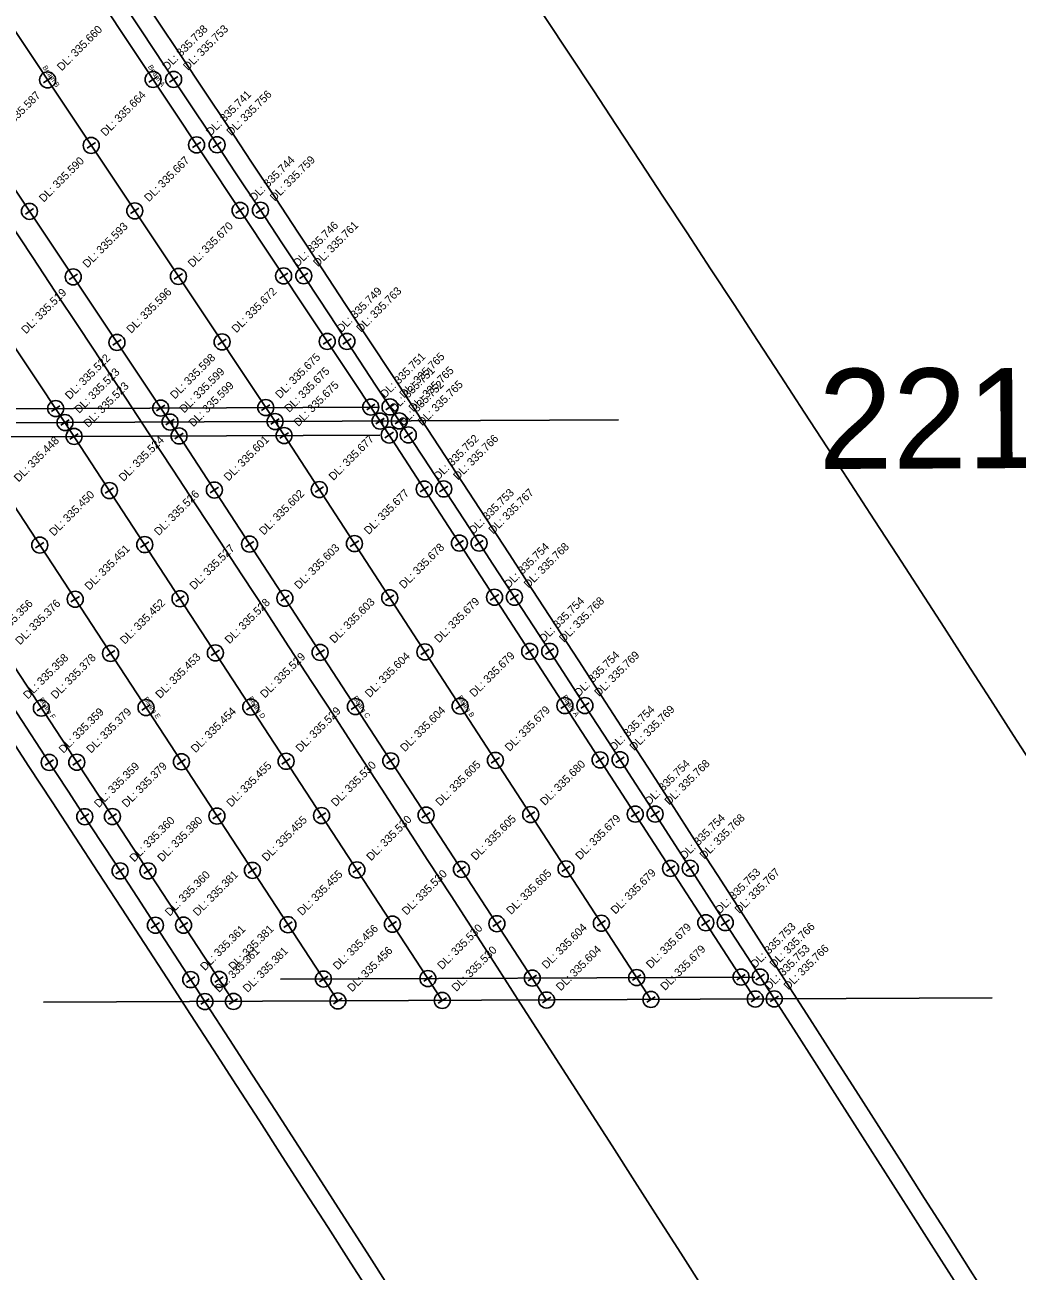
# Model space of a CAD drawing. Extents: x 1524497 to 1524592, y 1103688 to 1103812.
# Drawn here: x 1524545.51 to 1524570.33, y 1103718.69 to 1103749.84 of the extents above; entities that cross this region are included whole.
import ezdxf

# ---------------------------------------------------------------- set-up
doc = ezdxf.new("R2010")
doc.units = 0
doc.layers.add('Level 1', color=7, linetype='Continuous')

msp = doc.modelspace()

# ---------------------------------------------------------------- linework, layer by layer
at = {"layer": 'Level 1'}
for p, q in [((1524535.113, 1103756.948), (1524546.512, 1103739.9)), ((1524537.761, 1103756.96), (1524549.14, 1103739.912)), ((1524540.409, 1103756.972), (1524551.767, 1103739.924)), ((1524543.057, 1103756.984), (1524554.394, 1103739.936)), ((1524545.974, 1103748.394), (1524546.182, 1103748.533)), ((1524548.611, 1103748.406), (1524548.819, 1103748.545)), ((1524549.334, 1103748.547), (1524549.126, 1103748.409)), ((1524547.063, 1103746.759), (1524547.271, 1103746.897)), ((1524549.699, 1103746.771), (1524549.907, 1103746.909)), ((1524550.42, 1103746.912), (1524550.212, 1103746.773)), ((1524545.52, 1103745.109), (1524545.728, 1103745.248)), ((1524548.154, 1103745.122), (1524548.362, 1103745.26)), ((1524550.788, 1103745.134), (1524550.996, 1103745.272)), ((1524551.505, 1103745.275), (1524551.296, 1103745.137)), ((1524546.613, 1103743.471), (1524546.821, 1103743.61)), ((1524549.245, 1103743.484), (1524549.453, 1103743.622)), ((1524551.877, 1103743.496), (1524552.085, 1103743.634)), ((1524552.587, 1103743.636), (1524552.379, 1103743.499)), ((1524547.708, 1103741.832), (1524547.916, 1103741.971)), ((1524550.337, 1103741.844), (1524550.545, 1103741.983)), ((1524552.967, 1103741.857), (1524553.175, 1103741.995)), ((1524553.668, 1103741.997), (1524553.459, 1103741.859)), ((1524546.175, 1103740.179), (1524546.383, 1103740.318)), ((1524548.803, 1103740.192), (1524549.011, 1103740.33)), ((1524551.43, 1103740.204), (1524551.638, 1103740.342)), ((1524554.058, 1103740.216), (1524554.266, 1103740.355)), ((1524554.747, 1103740.356), (1524554.538, 1103740.219)), ((1524554.382, 1103740.286), (1524542.44, 1103740.231)), ((1524554.29, 1103739.867), (1524554.498, 1103740.006)), ((1524554.29, 1103739.868), (1524554.499, 1103740.004)), ((1524554.976, 1103740.007), (1524554.767, 1103739.87)), ((1524554.976, 1103740.007), (1524554.767, 1103739.87)), ((1524560.354, 1103739.964), (1524536.471, 1103739.853)), ((1524541.257, 1103739.876), (1524550.726, 1103725.427)), ((1524543.885, 1103739.888), (1524553.337, 1103725.439)), ((1524546.407, 1103739.832), (1524546.617, 1103739.968)), ((1524546.408, 1103739.83), (1524546.616, 1103739.969)), ((1524546.512, 1103739.9), (1524555.948, 1103725.451)), ((1524549.035, 1103739.844), (1524549.244, 1103739.98)), ((1524549.036, 1103739.843), (1524549.243, 1103739.981)), ((1524549.14, 1103739.912), (1524558.558, 1103725.463)), ((1524551.662, 1103739.856), (1524551.872, 1103739.992)), ((1524551.663, 1103739.855), (1524551.871, 1103739.994)), ((1524551.767, 1103739.924), (1524561.169, 1103725.476)), ((1524554.394, 1103739.936), (1524563.779, 1103725.488)), ((1524554.385, 1103739.586), (1524542.444, 1103739.531)), ((1524546.635, 1103739.483), (1524546.845, 1103739.619)), ((1524549.262, 1103739.495), (1524549.472, 1103739.631)), ((1524551.889, 1103739.507), (1524552.099, 1103739.643)), ((1524554.516, 1103739.519), (1524554.726, 1103739.656)), ((1524555.205, 1103739.658), (1524554.996, 1103739.521)), ((1524547.518, 1103738.131), (1524547.727, 1103738.268)), ((1524550.143, 1103738.143), (1524550.353, 1103738.28)), ((1524552.769, 1103738.156), (1524552.978, 1103738.292)), ((1524555.394, 1103738.168), (1524555.604, 1103738.304)), ((1524556.091, 1103738.307), (1524555.881, 1103738.17)), ((1524545.777, 1103736.767), (1524545.986, 1103736.904)), ((1524548.401, 1103736.779), (1524548.61, 1103736.916)), ((1524551.025, 1103736.791), (1524551.234, 1103736.928)), ((1524553.649, 1103736.803), (1524553.858, 1103736.94)), ((1524556.272, 1103736.816), (1524556.482, 1103736.952)), ((1524556.975, 1103736.954), (1524556.766, 1103736.818)), ((1524546.662, 1103735.414), (1524546.872, 1103735.55)), ((1524549.285, 1103735.426), (1524549.494, 1103735.563)), ((1524551.907, 1103735.438), (1524552.116, 1103735.575)), ((1524554.529, 1103735.45), (1524554.739, 1103735.587)), ((1524557.151, 1103735.462), (1524557.361, 1103735.599)), ((1524557.858, 1103735.601), (1524557.649, 1103735.465)), ((1524547.548, 1103734.06), (1524547.757, 1103734.197)), ((1524550.169, 1103734.072), (1524550.378, 1103734.209)), ((1524552.789, 1103734.084), (1524552.999, 1103734.221)), ((1524555.41, 1103734.096), (1524555.62, 1103734.233)), ((1524558.031, 1103734.109), (1524558.24, 1103734.245)), ((1524558.74, 1103734.247), (1524558.531, 1103734.111)), ((1524548.434, 1103732.705), (1524548.644, 1103732.842)), ((1524551.053, 1103732.717), (1524551.263, 1103732.854)), ((1524553.672, 1103732.729), (1524553.882, 1103732.866)), ((1524556.292, 1103732.742), (1524556.501, 1103732.878)), ((1524558.911, 1103732.754), (1524559.12, 1103732.89)), ((1524559.621, 1103732.892), (1524559.412, 1103732.756)), ((1524545.815, 1103732.693), (1524546.024, 1103732.83)), ((1524546.223, 1103731.471), (1524546.014, 1103731.334)), ((1524546.704, 1103731.337), (1524546.913, 1103731.474)), ((1524549.321, 1103731.349), (1524549.53, 1103731.486)), ((1524551.939, 1103731.362), (1524552.148, 1103731.498)), ((1524554.556, 1103731.374), (1524554.766, 1103731.51)), ((1524557.174, 1103731.386), (1524557.383, 1103731.522)), ((1524559.791, 1103731.398), (1524560.001, 1103731.534)), ((1524560.501, 1103731.537), (1524560.291, 1103731.401)), ((1524547.11, 1103730.115), (1524546.9, 1103729.978)), ((1524547.593, 1103729.981), (1524547.802, 1103730.118)), ((1524550.208, 1103729.993), (1524550.418, 1103730.13)), ((1524552.824, 1103730.005), (1524553.034, 1103730.142)), ((1524555.44, 1103730.017), (1524555.65, 1103730.154)), ((1524558.056, 1103730.03), (1524558.266, 1103730.166)), ((1524560.672, 1103730.042), (1524560.882, 1103730.178)), ((1524561.379, 1103730.18), (1524561.169, 1103730.044)), ((1524556.325, 1103728.66), (1524556.534, 1103728.797)), ((1524558.939, 1103728.672), (1524559.149, 1103728.809)), ((1524561.554, 1103728.685), (1524561.763, 1103728.821)), ((1524562.256, 1103728.823), (1524562.046, 1103728.687)), ((1524547.995, 1103728.757), (1524547.786, 1103728.621)), ((1524548.482, 1103728.624), (1524548.691, 1103728.761)), ((1524551.096, 1103728.636), (1524551.306, 1103728.773)), ((1524553.711, 1103728.648), (1524553.92, 1103728.785)), ((1524548.879, 1103727.399), (1524548.67, 1103727.263)), ((1524549.372, 1103727.266), (1524549.581, 1103727.403)), ((1524551.985, 1103727.278), (1524552.194, 1103727.415)), ((1524554.597, 1103727.29), (1524554.807, 1103727.427)), ((1524557.21, 1103727.302), (1524557.42, 1103727.439)), ((1524559.823, 1103727.314), (1524560.033, 1103727.451)), ((1524562.436, 1103727.327), (1524562.645, 1103727.463)), ((1524563.132, 1103727.465), (1524562.922, 1103727.329)), ((1524549.762, 1103726.04), (1524549.553, 1103725.904)), ((1524550.262, 1103725.907), (1524550.472, 1103726.044)), ((1524563.766, 1103726.038), (1524551.901, 1103725.983)), ((1524552.874, 1103725.919), (1524553.083, 1103726.056)), ((1524555.485, 1103725.931), (1524555.694, 1103726.068)), ((1524558.096, 1103725.944), (1524558.305, 1103726.08)), ((1524560.707, 1103725.956), (1524560.917, 1103726.092)), ((1524563.318, 1103725.968), (1524563.528, 1103726.104)), ((1524564.006, 1103726.106), (1524563.796, 1103725.971)), ((1524569.702, 1103725.515), (1524545.971, 1103725.405)), ((1524550.118, 1103725.492), (1524549.909, 1103725.356)), ((1524550.622, 1103725.359), (1524550.831, 1103725.496)), ((1524553.232, 1103725.371), (1524553.442, 1103725.508)), ((1524555.843, 1103725.383), (1524556.052, 1103725.52)), ((1524558.453, 1103725.395), (1524558.663, 1103725.532)), ((1524561.064, 1103725.407), (1524561.274, 1103725.544)), ((1524563.675, 1103725.42), (1524563.884, 1103725.556)), ((1524564.359, 1103725.557), (1524564.148, 1103725.422))]:
    msp.add_line(p, q, dxfattribs=at)
for points in [[(1524546.571, 1103739.809), (1524546.564, 1103739.934), (1524546.512, 1103739.9)], [(1524549.199, 1103739.821), (1524549.192, 1103739.946), (1524549.14, 1103739.912)], [(1524551.826, 1103739.833), (1524551.819, 1103739.958), (1524551.767, 1103739.924)], [(1524554.453, 1103739.846), (1524554.447, 1103739.97), (1524554.394, 1103739.936)]]:
    msp.add_lwpolyline(points, dxfattribs=at)
for centre in [(1524546.078, 1103748.464), (1524548.715, 1103748.476), (1524549.23, 1103748.478), (1524547.167, 1103746.828), (1524549.803, 1103746.84), (1524550.316, 1103746.842), (1524545.624, 1103745.179), (1524548.258, 1103745.191), (1524550.892, 1103745.203), (1524551.401, 1103745.206), (1524546.717, 1103743.541), (1524549.349, 1103743.553), (1524551.981, 1103743.565), (1524552.483, 1103743.567), (1524547.812, 1103741.901), (1524550.441, 1103741.914), (1524553.071, 1103741.926), (1524553.564, 1103741.928), (1524546.279, 1103740.249), (1524548.907, 1103740.261), (1524551.534, 1103740.273), (1524554.162, 1103740.285), (1524554.642, 1103740.288), (1524546.512, 1103739.9), (1524546.512, 1103739.9), (1524549.14, 1103739.912), (1524549.14, 1103739.912), (1524551.767, 1103739.924), (1524551.767, 1103739.924), (1524554.394, 1103739.936), (1524554.394, 1103739.936), (1524554.871, 1103739.939), (1524554.871, 1103739.939), (1524546.74, 1103739.551), (1524549.367, 1103739.563), (1524551.994, 1103739.575), (1524554.621, 1103739.587), (1524555.1, 1103739.59), (1524547.623, 1103738.2), (1524550.248, 1103738.212), (1524552.873, 1103738.224), (1524555.499, 1103738.236), (1524555.986, 1103738.238), (1524545.882, 1103736.835), (1524548.506, 1103736.847), (1524551.129, 1103736.859), (1524553.753, 1103736.872), (1524556.377, 1103736.884), (1524556.871, 1103736.886), (1524546.767, 1103735.482), (1524549.389, 1103735.494), (1524552.012, 1103735.506), (1524554.634, 1103735.518), (1524557.256, 1103735.531), (1524557.754, 1103735.533), (1524547.653, 1103734.128), (1524550.273, 1103734.14), (1524552.894, 1103734.152), (1524555.515, 1103734.164), (1524558.136, 1103734.177), (1524558.636, 1103734.179), (1524545.92, 1103732.761), (1524548.539, 1103732.773), (1524551.158, 1103732.786), (1524553.777, 1103732.798), (1524556.396, 1103732.81), (1524559.015, 1103732.822), (1524559.516, 1103732.824), (1524546.118, 1103731.403), (1524546.808, 1103731.406), (1524549.426, 1103731.418), (1524552.043, 1103731.43), (1524554.661, 1103731.442), (1524557.278, 1103731.454), (1524559.896, 1103731.466), (1524560.396, 1103731.469), (1524547.005, 1103730.046), (1524547.697, 1103730.049), (1524550.313, 1103730.062), (1524552.929, 1103730.074), (1524555.545, 1103730.086), (1524558.161, 1103730.098), (1524560.777, 1103730.11), (1524561.274, 1103730.112), (1524547.891, 1103728.689), (1524548.587, 1103728.692), (1524551.201, 1103728.704), (1524553.815, 1103728.716), (1524556.43, 1103728.729), (1524559.044, 1103728.741), (1524561.659, 1103728.753), (1524562.151, 1103728.755), (1524552.089, 1103727.346), (1524554.702, 1103727.359), (1524557.315, 1103727.371), (1524559.928, 1103727.383), (1524562.541, 1103727.395), (1524563.027, 1103727.397), (1524548.775, 1103727.331), (1524549.477, 1103727.334), (1524549.658, 1103725.972), (1524550.367, 1103725.976), (1524552.978, 1103725.988), (1524555.59, 1103726), (1524558.201, 1103726.012), (1524560.812, 1103726.024), (1524563.423, 1103726.036), (1524563.901, 1103726.038), (1524561.169, 1103725.476), (1524563.779, 1103725.488), (1524564.253, 1103725.49), (1524550.013, 1103725.424), (1524550.726, 1103725.427), (1524553.337, 1103725.439), (1524555.948, 1103725.451), (1524558.558, 1103725.463)]:
    msp.add_circle(centre, 0.2, dxfattribs=at)
for radius in [1750, 1750, 1750, 1750, 1750, 1750, 1750, 1750, 1741.88, 1741.88, 1741.88, 1741.88, 1741.88, 1741.88, 1741.88, 1741.88, 1741.4, 1741.4, 1741.4, 1741.4, 1741.4, 1741.4, 1741.4, 1741.4, 1736, 1736, 1736, 1736, 1736, 1736, 1736, 1736, 1729.4, 1729.4, 1729.4, 1729.4, 1729.4, 1729.4, 1729.4, 1729.4, 1728.92, 1728.92, 1728.92, 1728.92, 1728.92, 1728.92, 1728.92, 1728.92]:
    msp.add_arc((1523099.068, 1102784.371), radius, 31.492411, 33.735131, dxfattribs=at)

# ---------------------------------------------------------------- texts
for s, height, rotation, p in [('DL: 335.660', 0.2, 45, (1524546.431, 1103748.676)), ('DL: 335.738', 0.2, 45, (1524549.069, 1103748.688)), ('DL: 335.753', 0.2, 45, (1524549.584, 1103748.69)), ('Beam B', 0.125, 303.6739, (1524545.945, 1103748.776)), ('Beam A', 0.125, 303.6257, (1524548.581, 1103748.79)), ('DL: 335.587', 0.2, 45, (1524544.885, 1103747.028)), ('DL: 335.664', 0.2, 45, (1524547.521, 1103747.04)), ('DL: 335.741', 0.2, 45, (1524550.157, 1103747.052)), ('DL: 335.756', 0.2, 45, (1524550.67, 1103747.055)), ('DL: 335.667', 0.2, 45, (1524548.611, 1103745.403)), ('DL: 335.744', 0.2, 45, (1524551.245, 1103745.415)), ('DL: 335.759', 0.2, 45, (1524551.754, 1103745.418)), ('DL: 335.590', 0.2, 45, (1524545.978, 1103745.391)), ('DL: 335.593', 0.2, 45, (1524547.071, 1103743.753)), ('DL: 335.670', 0.2, 45, (1524549.703, 1103743.765)), ('DL: 335.746', 0.2, 45, (1524552.335, 1103743.777)), ('DL: 335.761', 0.2, 45, (1524552.837, 1103743.78)), ('DL: 335.519', 0.2, 45, (1524545.535, 1103742.101)), ('DL: 335.596', 0.2, 45, (1524548.165, 1103742.114)), ('DL: 335.672', 0.2, 45, (1524550.795, 1103742.126)), ('DL: 335.749', 0.2, 45, (1524553.425, 1103742.138)), ('DL: 335.763', 0.2, 45, (1524553.917, 1103742.14)), ('DL: 335.522', 0.2, 45, (1524546.632, 1103740.461)), ('DL: 335.598', 0.2, 45, (1524549.26, 1103740.473)), ('DL: 335.675', 0.2, 45, (1524551.888, 1103740.485)), ('DL: 335.751', 0.2, 45, (1524554.516, 1103740.497)), ('DL: 335.765', 0.2, 45, (1524554.996, 1103740.5)), ('DL: 335.523', 0.2, 45, (1524546.866, 1103740.112)), ('DL: 335.523', 0.2, 45, (1524546.866, 1103740.112)), ('DL: 335.599', 0.2, 45, (1524549.493, 1103740.124)), ('DL: 335.599', 0.2, 45, (1524549.493, 1103740.124)), ('DL: 335.675', 0.2, 45, (1524552.12, 1103740.136)), ('DL: 335.675', 0.2, 45, (1524552.12, 1103740.136)), ('DL: 335.751', 0.2, 45, (1524554.748, 1103740.149)), ('DL: 335.751', 0.2, 45, (1524554.748, 1103740.149)), ('DL: 335.765', 0.2, 45, (1524555.225, 1103740.151)), ('DL: 335.765', 0.2, 45, (1524555.225, 1103740.151)), ('221+33.853', 2.5, 0.265, (1524565.36, 1103738.737)), ('DL: 335.675', 0.2, 45, (1524552.348, 1103739.787)), ('DL: 335.752', 0.2, 45, (1524554.975, 1103739.8)), ('DL: 335.765', 0.2, 45, (1524555.454, 1103739.802)), ('DL: 335.523', 0.2, 45, (1524547.094, 1103739.763)), ('DL: 335.599', 0.2, 45, (1524549.721, 1103739.775)), ('DL: 335.448', 0.2, 45, (1524545.351, 1103738.4)), ('DL: 335.524', 0.2, 45, (1524547.976, 1103738.412)), ('DL: 335.601', 0.2, 45, (1524550.602, 1103738.424)), ('DL: 335.677', 0.2, 45, (1524553.227, 1103738.436)), ('DL: 335.752', 0.2, 45, (1524555.852, 1103738.448)), ('DL: 335.766', 0.2, 45, (1524556.34, 1103738.45)), ('DL: 335.450', 0.2, 45, (1524546.235, 1103737.047)), ('DL: 335.526', 0.2, 45, (1524548.859, 1103737.059)), ('DL: 335.602', 0.2, 45, (1524551.483, 1103737.072)), ('DL: 335.677', 0.2, 45, (1524554.107, 1103737.084)), ('DL: 335.753', 0.2, 45, (1524556.731, 1103737.096)), ('DL: 335.767', 0.2, 45, (1524557.224, 1103737.098)), ('DL: 335.754', 0.2, 45, (1524557.61, 1103735.743)), ('DL: 335.768', 0.2, 45, (1524558.107, 1103735.745)), ('DL: 335.451', 0.2, 45, (1524547.121, 1103735.694)), ('DL: 335.527', 0.2, 45, (1524549.743, 1103735.706)), ('DL: 335.603', 0.2, 45, (1524552.365, 1103735.718)), ('DL: 335.678', 0.2, 45, (1524554.987, 1103735.731)), ('DL: 335.356', 0.2, 45, (1524544.694, 1103734.325)), ('DL: 335.376', 0.2, 45, (1524545.386, 1103734.328)), ('DL: 335.452', 0.2, 45, (1524548.006, 1103734.34)), ('DL: 335.528', 0.2, 45, (1524550.627, 1103734.352)), ('DL: 335.603', 0.2, 45, (1524553.248, 1103734.365)), ('DL: 335.679', 0.2, 45, (1524555.868, 1103734.377)), ('DL: 335.754', 0.2, 45, (1524558.489, 1103734.389)), ('DL: 335.768', 0.2, 45, (1524558.989, 1103734.391)), ('DL: 335.358', 0.2, 45, (1524545.584, 1103732.97)), ('DL: 335.378', 0.2, 45, (1524546.273, 1103732.973)), ('DL: 335.453', 0.2, 45, (1524548.892, 1103732.986)), ('DL: 335.529', 0.2, 45, (1524551.512, 1103732.998)), ('DL: 335.604', 0.2, 45, (1524554.131, 1103733.01)), ('DL: 335.679', 0.2, 45, (1524556.75, 1103733.022)), ('DL: 335.754', 0.2, 45, (1524559.369, 1103733.034)), ('DL: 335.769', 0.2, 45, (1524559.87, 1103733.036)), ('Beam F', 0.125, 303.2399, (1524545.853, 1103732.978)), ('Beam E', 0.125, 303.1931, (1524548.471, 1103732.992)), ('Beam D', 0.125, 303.1462, (1524551.09, 1103733.005)), ('Beam C', 0.125, 303.0993, (1524553.709, 1103733.017)), ('Beam B', 0.125, 303.0523, (1524556.328, 1103733.029)), ('Beam A', 0.125, 303.0053, (1524558.946, 1103733.043)), ('DL: 335.359', 0.2, 45, (1524546.472, 1103731.615)), ('DL: 335.379', 0.2, 45, (1524547.162, 1103731.618)), ('DL: 335.454', 0.2, 45, (1524549.779, 1103731.63)), ('DL: 335.529', 0.2, 45, (1524552.397, 1103731.642)), ('DL: 335.604', 0.2, 45, (1524555.014, 1103731.654)), ('DL: 335.679', 0.2, 45, (1524557.632, 1103731.666)), ('DL: 335.754', 0.2, 45, (1524560.25, 1103731.678)), ('DL: 335.769', 0.2, 45, (1524560.749, 1103731.681)), ('DL: 335.359', 0.2, 45, (1524547.359, 1103730.258)), ('DL: 335.379', 0.2, 45, (1524548.051, 1103730.262)), ('DL: 335.455', 0.2, 45, (1524550.667, 1103730.274)), ('DL: 335.530', 0.2, 45, (1524553.283, 1103730.286)), ('DL: 335.605', 0.2, 45, (1524555.899, 1103730.298)), ('DL: 335.680', 0.2, 45, (1524558.515, 1103730.31)), ('DL: 335.754', 0.2, 45, (1524561.131, 1103730.322)), ('DL: 335.768', 0.2, 45, (1524561.628, 1103730.324)), ('DL: 335.360', 0.2, 45, (1524548.244, 1103728.901)), ('DL: 335.380', 0.2, 45, (1524548.94, 1103728.904)), ('DL: 335.455', 0.2, 45, (1524551.554, 1103728.917)), ('DL: 335.530', 0.2, 45, (1524554.169, 1103728.929)), ('DL: 335.605', 0.2, 45, (1524556.783, 1103728.941)), ('DL: 335.679', 0.2, 45, (1524559.398, 1103728.953)), ('DL: 335.754', 0.2, 45, (1524562.012, 1103728.965)), ('DL: 335.768', 0.2, 45, (1524562.504, 1103728.967)), ('DL: 335.360', 0.2, 45, (1524549.128, 1103727.543)), ('DL: 335.381', 0.2, 45, (1524549.83, 1103727.546)), ('DL: 335.455', 0.2, 45, (1524552.443, 1103727.559)), ('DL: 335.530', 0.2, 45, (1524555.056, 1103727.571)), ('DL: 335.605', 0.2, 45, (1524557.669, 1103727.583)), ('DL: 335.679', 0.2, 45, (1524560.281, 1103727.595)), ('DL: 335.753', 0.2, 45, (1524562.894, 1103727.607)), ('DL: 335.767', 0.2, 45, (1524563.38, 1103727.609)), ('DL: 335.361', 0.2, 45, (1524550.011, 1103726.184)), ('DL: 335.381', 0.2, 45, (1524550.721, 1103726.188)), ('DL: 335.456', 0.2, 45, (1524553.332, 1103726.2)), ('DL: 335.530', 0.2, 45, (1524555.943, 1103726.212)), ('DL: 335.604', 0.2, 45, (1524558.554, 1103726.224)), ('DL: 335.679', 0.2, 45, (1524561.166, 1103726.236)), ('DL: 335.753', 0.2, 45, (1524563.777, 1103726.248)), ('DL: 335.766', 0.2, 45, (1524564.255, 1103726.25)), ('DL: 335.361', 0.2, 45, (1524550.367, 1103725.636)), ('DL: 335.381', 0.2, 45, (1524551.08, 1103725.639)), ('DL: 335.456', 0.2, 45, (1524553.691, 1103725.651)), ('DL: 335.530', 0.2, 45, (1524556.301, 1103725.663)), ('DL: 335.604', 0.2, 45, (1524558.912, 1103725.676)), ('DL: 335.679', 0.2, 45, (1524561.522, 1103725.688)), ('DL: 335.753', 0.2, 45, (1524564.133, 1103725.7)), ('DL: 335.766', 0.2, 45, (1524564.607, 1103725.702))]:
    msp.add_text(s, height=height, rotation=rotation, dxfattribs=at).set_placement(p)

doc.saveas('drawing.dxf')
